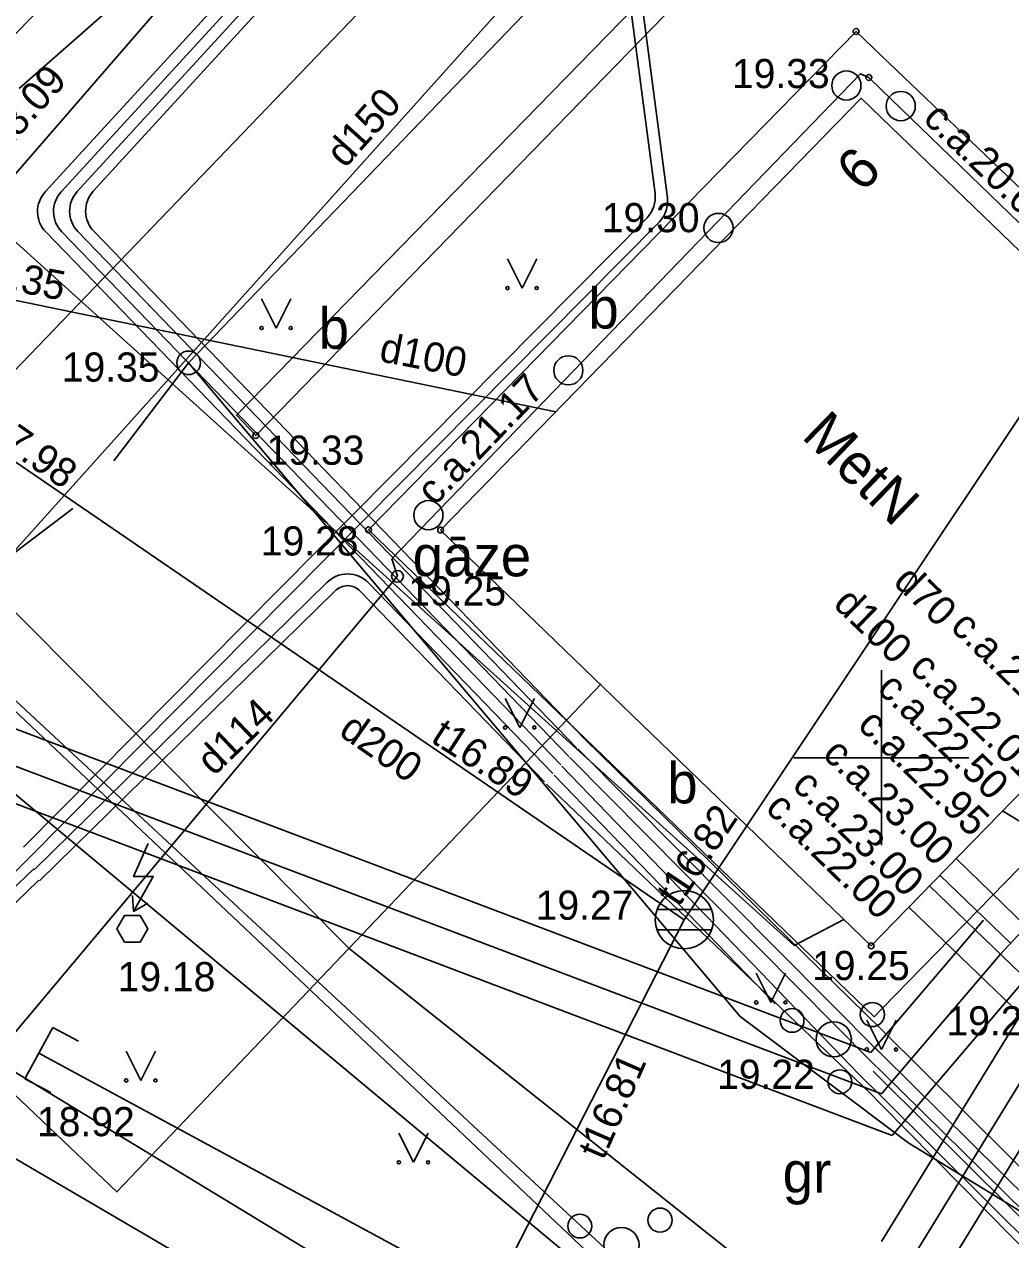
# Model space of a CAD drawing. Extents: x 532933 to 533143, y 328014 to 328163.
# Drawn here: x 532985.32 to 533002.21, y 328041.74 to 328062.57 of the extents above; entities that cross this region are included whole.
import ezdxf

# ---------------------------------------------------------------- set-up
doc = ezdxf.new("R2010")
doc.units = 0
for name, color, linetype in [('BUVE_EKAS_####_####_#', 7, 'Continuous'), ('BUVE_EKAS_ADRS_TKST_#', 7, 'Continuous'), ('BUVE_EKAS_RAKS_TKST_#', 7, 'Continuous'), ('BUVE_ELEM_####_####_#', 7, 'Continuous'), ('CELI_CMAL_####_####_#', 7, 'Continuous'), ('CELI_CSEG_####_TKST_#', 7, 'Continuous'), ('CKOM_ELEM_####_####_#', 7, 'Continuous'), ('ELEK_VADP_NEDR_####_#', 7, 'Continuous'), ('ELEK_VADP_VSPR_####_#', 7, 'Continuous'), ('ELEK_VADP_ZSPR_####_#', 7, 'Continuous'), ('GAZE_ELEM_####_####_#', 7, 'Continuous'), ('GAZE_ELEM_####_TKST_#', 7, 'Continuous'), ('GAZE_VADP_ASP1_####_I', 7, 'Continuous'), ('GAZE_VADP_ASP1_TKST_I', 7, 'Continuous'), ('GAZE_VADP_NEDR_####_#', 7, 'Continuous'), ('GAZE_VADV_ASP1_####_#', 7, 'Continuous'), ('GAZE_VADV_ASP1_TKST_#', 7, 'Continuous'), ('GEOD_ELEM_####_####_#', 7, 'Continuous'), ('LKAN_ELEM_####_####_#', 7, 'Continuous'), ('LKAN_ELEM_PAST_TKST_#', 7, 'Continuous'), ('LKAN_VADP_PAST_####_#', 7, 'Continuous'), ('LKAN_VADP_PAST_TKST_#', 7, 'Continuous'), ('NORB_ELEM_####_####_#', 7, 'Continuous'), ('NORB_ZOGS_BARJ_####_#', 7, 'Continuous'), ('NORB_ZOGS_ZSTP_####_#', 7, 'Continuous'), ('RELJ_AATZ_####_TKST_#', 7, 'Continuous'), ('RELJ_ELEM_####_####_#', 7, 'Continuous'), ('ROBZ_UZMR_####_####_#', 7, 'Continuous'), ('SAKT_VADP_KABE_####_#', 7, 'Continuous'), ('SILT_VADP_UDEN_####_#', 7, 'Continuous'), ('SILT_VADP_UDEN_TKAM_#', 7, 'Continuous'), ('SILT_VADV_UDEN_####_#', 7, 'Continuous'), ('SILT_VADV_UDEN_TKST_#', 7, 'Continuous'), ('SKAN_VADP_PAST_####_#', 7, 'Continuous'), ('SKAN_VADP_PAST_TKST_#', 7, 'Continuous'), ('TERT_ELEM_####_####_#', 7, 'Continuous'), ('TERT_KRND_####_####_#', 7, 'Continuous'), ('UDTK_VADP_UDEN_####_#', 7, 'Continuous'), ('UDTK_VADP_UDEN_TKST_#', 7, 'Continuous')]:
    doc.layers.add(name, color=color, linetype=linetype)

msp = doc.modelspace()

# ---------------------------------------------------------------- linework, layer by layer
at = {"layer": 'BUVE_EKAS_####_####_#'}
for p, q in [((532999.651, 328061.302), (532992.45, 328053.901)), ((533000, 328060.965), (532999.651, 328061.302)), ((533007.034, 328054.184), (533000, 328060.965)), ((533000, 328046.956), (533007.034, 328054.184)), ((532992.45, 328053.901), (532999.825, 328046.776)), ((532999.825, 328046.776), (533000, 328046.956))]:
    msp.add_line(p, q, dxfattribs=at)
at = {"layer": 'BUVE_ELEM_####_####_#'}
for centre in [(532999.4, 328061.518), (533000.331, 328061.166), (532997.209, 328059.078), (532994.638, 328056.638), (532992.241, 328054.156)]:
    msp.add_circle(centre, 0.25, dxfattribs=at)
at = {"layer": 'CELI_CMAL_####_####_#'}
for points in [[(533000, 328067.199), (532988.954, 328055.872), (532989.285, 328055.52), (533000, 328066.543)], [(532991.217, 328053.906), (532999.566, 328062.445), (533000, 328062.03)], [(533000, 328062.03), (533008.25, 328054.143)], [(532971.073, 328061.066), (532974.996, 328053.804), (532983.457, 328045.647), (532997.471, 328037.127), (533000, 328035.732)], [(532988.134, 328056.767), (532997.581, 328045.566), (533000.47, 328043.392), (533005, 328040.625), (533007.859, 328041.253), (533010.858, 328043.033), (533013.229, 328045.301), (533015.914, 328043.382), (533018.913, 328040.311), (533019.227, 328038.915), (533018.286, 328036.96), (533015.914, 328034.657), (533011.586, 328033.95), (533007.336, 328035.18), (533001.373, 328038.391), (532990.886, 328046.732), (532984.581, 328053.078)], [(533000, 328045.688), (533008.25, 328054.143)], [(532991.217, 328053.906), (532999.877, 328045.562), (533000, 328045.688)]]:
    msp.add_lwpolyline(points, dxfattribs=at)
at = {"layer": 'CKOM_ELEM_####_####_#'}
msp.add_line((532987.193, 328047.366), (532987.434, 328047.505), dxfattribs=at)
msp.add_lwpolyline([(532987.442, 328048.528), (532987.193, 328047.965), (532987.529, 328047.965), (532987.193, 328047.366), (532987.171, 328047.636)], dxfattribs=at)
msp.add_lwpolyline([(532987.037, 328046.836), (532987.303, 328046.836), (532987.436, 328047.066), (532987.303, 328047.297), (532987.037, 328047.297), (532986.904, 328047.066)], close=True, dxfattribs=at)
at = {"layer": 'ELEK_VADP_NEDR_####_#'}
for p, q in [((532990.498, 328052.996), (532985.489, 328048.079)), ((532990.638, 328052.853), (532985.579, 328047.888)), ((532994.924, 328050.309), (533000, 328045.345)), ((532994.799, 328050.152), (532999.962, 328044.956)), ((532994.658, 328050.01), (532999.846, 328044.771)), ((532994.397, 328049.702), (532998.183, 328045.782)), ((532994.266, 328049.549), (532999.799, 328044.257)), ((532999.625, 328044.568), (533000, 328044.195)), ((532999.799, 328044.257), (533000, 328044.054)), ((533000, 328044.195), (533020.885, 328023.4)), ((533000, 328044.054), (533020.527, 328023.205))]:
    msp.add_line(p, q, dxfattribs=at)
for points in [[(532995.483, 328070.395), (532985.678, 328059.695)], [(532995.76, 328070.402), (532985.952, 328059.699)], [(532996.038, 328070.409), (532986.227, 328059.702)], [(532996.316, 328070.417), (532986.502, 328059.706)], [(532985.687, 328059.01), (532994.509, 328049.875)], [(532985.961, 328059.014), (532994.648, 328050.02)], [(532986.236, 328059.017), (532994.786, 328050.165)], [(532986.511, 328059.021), (532994.918, 328050.315)], [(532991.217, 328052.996), (532992.707, 328051.453)], [(532991.217, 328052.995), (532994.37, 328049.729)], [(532991.073, 328052.856), (532994.232, 328049.584)], [(532994.528, 328049.856), (532999.625, 328044.568)], [(532975.982, 328042.686), (532976.247, 328042.975), (532985.068, 328047.695), (532985.481, 328048.096)], [(532976.179, 328042.603), (532976.372, 328042.814), (532985.188, 328047.532), (532985.571, 328047.904)], [(533000, 328045.345), (533021.675, 328023.83)], [(532999.891, 328045.026), (533000, 328044.918)], [(533000, 328044.918), (533021.444, 328023.704)], [(532999.846, 328044.771), (533000, 328044.62)], [(532999.857, 328044.63), (533000, 328044.488)], [(533000, 328044.62), (533018.606, 328026.308)], [(533000, 328044.488), (533021.116, 328023.525)]]:
    msp.add_lwpolyline(points, dxfattribs=at)
for centre, radius, start, end in [((532986.047, 328059.358), 0.5, 137.4991, 223.9999), ((532986.321, 328059.361), 0.5, 137.4991, 223.9999), ((532986.596, 328059.365), 0.5, 137.4991, 223.9999), ((532986.87, 328059.368), 0.5, 137.4991, 223.9999), ((532990.857, 328052.648), 0.5, 43.9999, 135.9896), ((532990.857, 328052.648), 0.3, 43.9999, 135.9896)]:
    msp.add_arc(centre, radius, start, end, dxfattribs=at)
at = {"layer": 'ELEK_VADP_VSPR_####_#'}
for p, q in [((532983.183, 328054.585), (532995.463, 328067.37)), ((532995.987, 328059.254), (532985.309, 328048.465)), ((532996.198, 328059.184), (532985.395, 328048.28))]:
    msp.add_line(p, q, dxfattribs=at)
for points in [[(532996.123, 328059.666), (532995.207, 328066.646)], [(532996.334, 328059.596), (532995.415, 328066.604)], [(532975.786, 328042.767), (532976.124, 328043.135), (532985.01, 328047.89), (532985.395, 328048.279)]]:
    msp.add_lwpolyline(points, dxfattribs=at)
for centre in [(532995.627, 328059.601), (532995.838, 328059.531)]:
    msp.add_arc(centre, 0.5, 315.9896, 7.4718, dxfattribs=at)
at = {"layer": 'ELEK_VADP_ZSPR_####_#'}
for points in [[(532994.175, 328069.331), (532985.231, 328061.466)], [(532999.357, 328047.227), (532998.507, 328046.78), (532981.807, 328061.871)]]:
    msp.add_lwpolyline(points, dxfattribs=at)
at = {"layer": 'GAZE_ELEM_####_####_#'}
for p, q in [((532985.809, 328045.378), (532985.332, 328044.499)), ((532986.248, 328045.14), (532985.809, 328045.378)), ((532985.772, 328044.261), (532985.332, 328044.499))]:
    msp.add_line(p, q, dxfattribs=at)
msp.add_circle((532991.712, 328053.108), 0.1, dxfattribs=at)
at = {"layer": 'GAZE_VADP_ASP1_####_I'}
msp.add_line((532991.712, 328053.108), (532983.933, 328043.83), dxfattribs=at)
msp.add_lwpolyline([(532984.115, 328043.743), (533000, 328034.443)], dxfattribs=at)
at = {"layer": 'GAZE_VADP_NEDR_####_#'}
msp.add_lwpolyline([(532985.57, 328044.939), (532999.86, 328037.197), (533000, 328037.117)], dxfattribs=at)
at = {"layer": 'GAZE_VADV_ASP1_####_#'}
msp.add_line((532991.615, 328053.409), (532991.712, 328053.108), dxfattribs=at)
for points in [[(532991.615, 328053.409), (532999.643, 328061.721), (532999.784, 328061.655), (533000, 328061.446)], [(533000, 328061.446), (533007.435, 328054.257)]]:
    msp.add_lwpolyline(points, dxfattribs=at)
at = {"layer": 'GEOD_ELEM_####_####_#'}
for p, q in [((533000, 328051.5), (533000, 328050)), ((532998.5, 328050), (533000, 328050)), ((533000, 328050), (533000, 328048.5)), ((533000, 328050), (533001.5, 328050))]:
    msp.add_line(p, q, dxfattribs=at)
at = {"layer": 'LKAN_ELEM_####_####_#'}
for p, q in [((532996.156, 328047.398), (532997.092, 328047.398)), ((532996.156, 328047.048), (532997.092, 328047.048))]:
    msp.add_line(p, q, dxfattribs=at)
msp.add_circle((532996.624, 328047.223), 0.5, dxfattribs=at)
at = {"layer": 'LKAN_VADP_PAST_####_#'}
for p, q in [((533006.239, 328061.66), (533000, 328052.292)), ((532983.864, 328055.963), (532996.624, 328047.223)), ((533000, 328052.292), (532996.624, 328047.223)), ((532996.624, 328047.223), (532990.537, 328035.344))]:
    msp.add_line(p, q, dxfattribs=at)
at = {"layer": 'NORB_ELEM_####_####_#'}
msp.add_circle((532988.134, 328056.767), 0.202, dxfattribs=at)
at = {"layer": 'NORB_ZOGS_BARJ_####_#'}
for p, q in [((532988.134, 328056.767), (532986.856, 328055.088)), ((532984.581, 328053.078), (532986.149, 328054.27))]:
    msp.add_line(p, q, dxfattribs=at)
at = {"layer": 'NORB_ZOGS_ZSTP_####_#'}
msp.add_line((532988.134, 328056.767), (533000, 328069.113), dxfattribs=at)
msp.add_lwpolyline([(532983.808, 328052.237), (532997.278, 328039.721)], dxfattribs=at)
at = {"layer": 'RELJ_ELEM_####_####_#'}
for centre in [(532999.566, 328062.445), (532999.784, 328061.655), (532989.285, 328055.52), (532991.217, 328053.906), (532992.45, 328053.901), (532999.825, 328046.776)]:
    msp.add_circle(centre, 0.05, dxfattribs=at)
at = {"layer": 'ROBZ_UZMR_####_####_#'}
for points in [[(532954.932, 328051.068), (532962.791, 328075.982), (532977.358, 328090.737), (532984.352, 328083.929), (532990.879, 328090.61), (533001.874, 328079.871), (532999.253, 328076.841), (532993.949, 328071.405), (532979.271, 328056.364), (532968.026, 328044.841)], [(532979.271, 328056.364), (532993.949, 328071.405), (533030.421, 328036.082), (533029.157, 328030.58), (533020.389, 328026.352), (532998.604, 328038.086)]]:
    msp.add_lwpolyline(points, close=True, dxfattribs=at)
msp.add_lwpolyline([(532952.676, 328043.916), (532954.932, 328051.068), (532968.026, 328044.841), (532979.271, 328056.364), (532998.604, 328038.086), (533020.389, 328026.352), (533032.36, 328019.904)], dxfattribs=at)
at = {"layer": 'SAKT_VADP_KABE_####_#'}
msp.add_lwpolyline([(532978.273, 328058.231), (532974.357, 328054.515), (532986.104, 328043.323), (532986.906, 328042.559), (532995.203, 328051.267)], dxfattribs=at)
at = {"layer": 'SILT_VADP_UDEN_####_#'}
for p, q in [((533000, 328044.239), (532967.835, 328056.416)), ((533003.444, 328048.152), (533002.038, 328046.631)), ((533000, 328044.239), (533002.038, 328046.631))]:
    msp.add_line(p, q, dxfattribs=at)
msp.add_lwpolyline([(533002.877, 328045.822), (533003.003, 328045.454), (533000, 328040.564)], dxfattribs=at)
at = {"layer": 'SILT_VADP_UDEN_TKAM_#'}
for p, q in [((532999.817, 328044.95), (532986.087, 328050.147)), ((533000, 328043.597), (532985.663, 328049.025)), ((533001.75, 328047.218), (533000, 328045.164)), ((533002.663, 328046.44), (533000.183, 328043.528)), ((533000, 328045.164), (532999.817, 328044.95)), ((533000.183, 328043.528), (533000, 328043.597))]:
    msp.add_line(p, q, dxfattribs=at)
for points in [[(532986.087, 328050.147), (532968.048, 328056.976), (532958.307, 328060.714)], [(532985.663, 328049.025), (532967.621, 328055.855), (532957.878, 328059.593)], [(533003.445, 328046.015), (533003.662, 328045.38), (533000, 328039.417)], [(533002.309, 328045.628), (533002.344, 328045.527), (533000, 328041.711)]]:
    msp.add_lwpolyline(points, dxfattribs=at)
at = {"layer": 'SILT_VADV_UDEN_####_#'}
for p, q in [((533002.074, 328049.088), (533005.473, 328047.022)), ((533001.281, 328048.272), (533004.689, 328044.955)), ((533001.009, 328047.984), (533002.206, 328046.829)), ((533000.829, 328047.798), (533002.877, 328045.822)), ((533000.478, 328047.434), (533003.843, 328044.186))]:
    msp.add_line(p, q, dxfattribs=at)
at = {"layer": 'SKAN_VADP_PAST_####_#'}
for points in [[(533000, 328076.986), (532997.194, 328073.892), (532983.572, 328058.168), (532980.848, 328060.709)], [(532983.572, 328058.168), (532994.423, 328055.929)]]:
    msp.add_lwpolyline(points, dxfattribs=at)
at = {"layer": 'TERT_ELEM_####_####_#'}
for p, q in [((532993.596, 328058.547), (532993.846, 328058.047)), ((532993.846, 328058.047), (532994.096, 328058.547)), ((532989.383, 328057.863), (532989.633, 328057.363)), ((532989.633, 328057.363), (532989.883, 328057.863)), ((532993.557, 328051.017), (532993.807, 328050.517)), ((532993.807, 328050.517), (532994.057, 328051.017)), ((532997.856, 328046.306), (532998.106, 328045.806)), ((532998.106, 328045.806), (532998.356, 328046.306)), ((532999.75, 328045.5), (533000, 328045)), ((533000, 328045), (533000.25, 328045.5)), ((532987.067, 328044.969), (532987.317, 328044.469)), ((532987.317, 328044.469), (532987.567, 328044.969)), ((532991.736, 328043.567), (532991.986, 328043.067)), ((532991.986, 328043.067), (532992.236, 328043.567))]:
    msp.add_line(p, q, dxfattribs=at)
for centre, radius in [((532993.596, 328058.047), 0.028), ((532994.096, 328058.047), 0.0263), ((532989.383, 328057.363), 0.028), ((532989.883, 328057.363), 0.0263), ((532993.557, 328050.517), 0.028), ((532994.057, 328050.517), 0.0263), ((532997.856, 328045.806), 0.028), ((532998.47, 328045.498), 0.204), ((532998.356, 328045.806), 0.0263), ((532999.846, 328045.599), 0.207), ((532999.184, 328045.174), 0.301), ((532999.75, 328045), 0.028), ((533000.25, 328045), 0.0263), ((532999.288, 328044.447), 0.205), ((532987.067, 328044.469), 0.028), ((532987.567, 328044.469), 0.0263), ((532991.736, 328043.066), 0.028), ((532992.236, 328043.066), 0.0263), ((532994.834, 328041.974), 0.204), ((532996.209, 328042.075), 0.207), ((532995.548, 328041.65), 0.301)]:
    msp.add_circle(centre, radius, dxfattribs=at)
at = {"layer": 'TERT_KRND_####_####_#'}
msp.add_line((532995.34, 328040.895), (532974.874, 328057.947), dxfattribs=at)
at = {"layer": 'UDTK_VADP_UDEN_####_#'}
msp.add_lwpolyline([(532996.68, 328066.401), (532981.413, 328049.383), (532974.784, 328043.51)], dxfattribs=at)

# ---------------------------------------------------------------- texts
at = {"layer": 'BUVE_EKAS_ADRS_TKST_#'}
msp.add_text('6', height=0.7, rotation=45.7821, dxfattribs=at).set_placement((532999.671, 328059.665))
at = {"layer": 'BUVE_EKAS_RAKS_TKST_#'}
msp.add_text('MetN', height=0.7, rotation=315.9855, dxfattribs=at).set_placement((532998.614, 328055.489))
at = {"layer": 'CELI_CSEG_####_TKST_#'}
for s, p in [(' b', (532994.721, 328057.354)), (' b', (532990.101, 328057.007)), (' b', (532996.072, 328049.217)), ('gr', (532998.309, 328042.548))]:
    msp.add_text(s, height=0.7, dxfattribs=at).set_placement(p)
at = {"layer": 'GAZE_ELEM_####_####_#'}
msp.add_text(' gāze', height=0.7, dxfattribs=at).set_placement((532991.712, 328053.108))
at = {"layer": 'GAZE_ELEM_####_TKST_#'}
msp.add_text(' 18.92', height=0.5, dxfattribs=at).set_placement((532985.352, 328043.514))
at = {"layer": 'GAZE_VADP_ASP1_TKST_I'}
msp.add_text('d114', height=0.5, rotation=43.6234, dxfattribs=at).set_placement((532988.565, 328049.673))
at = {"layer": 'GAZE_VADV_ASP1_TKST_#'}
for s, rotation, p in [('c.a.20.65', 315.9636, (533000.692, 328060.926)), ('c.a.21.17', 45.9952, (532992.348, 328054.3))]:
    msp.add_text(s, height=0.5, rotation=rotation, dxfattribs=at).set_placement(p)
at = {"layer": 'LKAN_ELEM_PAST_TKST_#'}
msp.add_text(' 19.27', height=0.5, dxfattribs=at).set_placement((532993.893, 328047.223))
at = {"layer": 'LKAN_VADP_PAST_TKST_#'}
for s, rotation, p in [('t17.98', 325.1225, (532984.468, 328055.651)), ('d200', 325.1225, (532990.685, 328050.4)), ('t16.89', 326.9883, (532992.259, 328050.285)), ('t16.82', 56.337, (532996.528, 328047.426)), ('t16.81', 66.432, (532995.241, 328043.086))]:
    msp.add_text(s, height=0.5, rotation=rotation, dxfattribs=at).set_placement(p)
at = {"layer": 'RELJ_AATZ_####_TKST_#'}
for s, p in [(' 19.33', (532997.255, 328061.474)), (' 19.30', (532995.026, 328059.005)), (' 19.35', (532985.777, 328056.444)), (' 19.33', (532989.285, 328055.02)), (' 19.28', (532989.185, 328053.465)), (' 19.25', (532991.712, 328052.608)), (' 19.18', (532986.734, 328045.998)), (' 19.25', (532998.627, 328046.189)), (' 19.21', (533000.929, 328045.241)), (' 19.22', (532997, 328044.325))]:
    msp.add_text(s, height=0.5, dxfattribs=at).set_placement(p)
at = {"layer": 'SILT_VADV_UDEN_TKST_#'}
for s, p in [('d70', (533000.184, 328052.99)), ('d100', (532999.155, 328052.61)), ('c.a.21.95', (533001.16, 328052.217)), ('c.a.22.01', (533000.462, 328051.514)), ('c.a.22.50', (532999.903, 328051.157)), ('c.a.22.95', (532999.57, 328050.534)), ('c.a.23.00', (532998.97, 328050.033)), ('c.a.23.00', (532998.449, 328049.502)), ('c.a.22.00', (532997.992, 328049.11))]:
    msp.add_text(s, height=0.5, rotation=315.8474, dxfattribs=at).set_placement(p)
at = {"layer": 'SKAN_VADP_PAST_TKST_#'}
for s, rotation, p in [('t18.09', 48.7139, (532984.846, 328060.196)), ('t18.35', 349.0523, (532984.143, 328058.185)), ('d100', 349.0523, (532991.381, 328056.797))]:
    msp.add_text(s, height=0.5, rotation=rotation, dxfattribs=at).set_placement(p)
at = {"layer": 'UDTK_VADP_UDEN_TKST_#'}
msp.add_text('d150', height=0.5, rotation=48.1029, dxfattribs=at).set_placement((532990.813, 328060.086))

doc.saveas('drawing.dxf')
